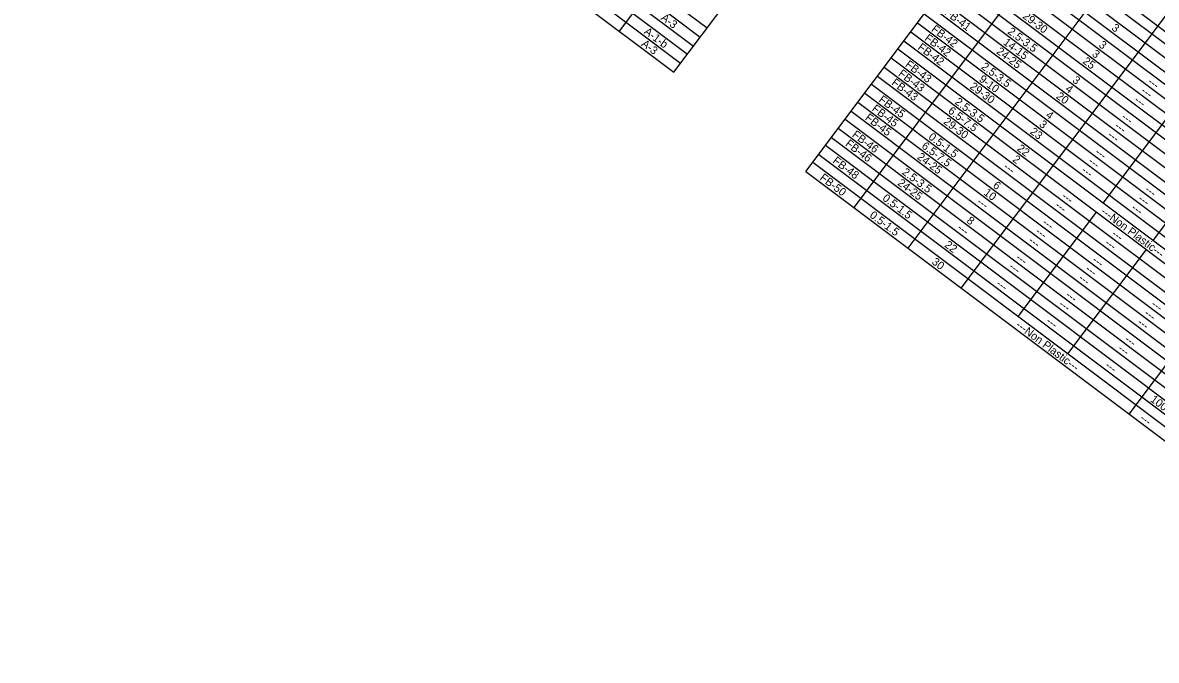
# Model space of a CAD drawing. Extents: x 627484.2 to 627517.5, y 367968.7 to 367996.9.
# Drawn here: x 627503.39 to 627511.18, y 367968.68 to 367973.07 of the extents above; entities that cross this region are included whole.
import ezdxf

# ---------------------------------------------------------------- set-up
doc = ezdxf.new("R2010")
doc.units = 0
doc.layers.add('Default', color=7, linetype='Continuous')

msp = doc.modelspace()

# ---------------------------------------------------------------- linework, layer by layer
at = {"layer": 'Default'}
for p, q in [((627503.5708, 367976.3272), (627508.046, 367972.9667)), ((627503.6176, 367976.3896), (627508.0929, 367973.0291)), ((627503.524, 367976.2648), (627507.9992, 367972.9043)), ((627503.483, 367976.2103), (627507.9582, 367972.8497)), ((627503.4361, 367976.1479), (627507.9114, 367972.7874)), ((627503.3893, 367976.0855), (627507.8646, 367972.725)), ((627507.8646, 367972.725), (627509.6531, 367975.1069)), ((627507.4903, 367973.006), (627508.8954, 367974.8772)), ((627508.7721, 367972.0435), (627510.5607, 367974.4254)), ((627509.1034, 367971.7947), (627510.892, 367974.1766)), ((627509.4738, 367971.5166), (627511.2623, 367973.8985)), ((627510.1245, 367973.8445), (627514.5997, 367970.484)), ((627510.0835, 367973.79), (627514.5588, 367970.4295)), ((627510.0367, 367973.7276), (627514.5119, 367970.3671)), ((627509.8402, 367971.2415), (627511.6288, 367973.6233)), ((627509.9489, 367973.6106), (627514.4241, 367970.2501)), ((627509.9898, 367973.6652), (627514.4651, 367970.3047)), ((627509.902, 367973.5483), (627514.3773, 367970.1878)), ((627509.8552, 367973.4859), (627514.3304, 367970.1254)), ((627509.7674, 367973.3689), (627514.2426, 367970.0084)), ((627509.8083, 367973.4235), (627514.2836, 367970.063)), ((627509.7205, 367973.3066), (627514.1958, 367969.9461)), ((627510.8156, 367971.8259), (627511.9162, 367973.2916)), ((627509.6737, 367973.2442), (627514.1489, 367969.8837)), ((627509.5859, 367973.1273), (627514.0611, 367969.7667)), ((627509.6269, 367973.1818), (627514.1021, 367969.8213)), ((627509.539, 367973.0649), (627514.0143, 367969.7044)), ((627509.4922, 367973.0025), (627513.9674, 367969.642)), ((627511.1586, 367971.5683), (627512.2593, 367973.034)), ((627509.4454, 367972.9401), (627513.9206, 367969.5796)), ((627509.3575, 367972.8232), (627513.8328, 367969.4627)), ((627509.4044, 367972.8856), (627513.8796, 367969.5251)), ((627509.3107, 367972.7608), (627513.786, 367969.4003)), ((627510.9941, 367970.375), (627512.7827, 367972.7568)), ((627509.2639, 367972.6984), (627513.7391, 367969.3379)), ((627509.1761, 367972.5815), (627513.6513, 367969.221)), ((627509.2229, 367972.6439), (627513.6981, 367969.2834)), ((627509.1292, 367972.5191), (627513.6045, 367969.1586)), ((627509.0824, 367972.4567), (627513.5576, 367969.0962)), ((627509.0414, 367972.4022), (627513.5166, 367969.0417)), ((627508.9477, 367972.2774), (627513.423, 367968.9169)), ((627508.9946, 367972.3398), (627513.4698, 367968.9793)), ((627508.9067, 367972.2228), (627513.382, 367968.8623)), ((627508.8599, 367972.1605), (627513.3352, 367968.8)), ((627508.7721, 367972.0435), (627513.2473, 367968.683)), ((627508.8189, 367972.1059), (627513.2942, 367968.7454)), ((627510.2301, 367971.0462), (627510.7687, 367971.7635)), ((627510.5732, 367970.7886), (627511.1118, 367971.5059))]:
    msp.add_line(p, q, dxfattribs=at)

# ---------------------------------------------------------------- texts
for s, p in [('FB-41', (627509.7204, 367973.126)), ('29-30', (627510.2571, 367973.1009)), ('A-3', (627507.7712, 367973.0899)), ('FB-42', (627509.6299, 367973.011)), ('3', (627510.8681, 367973.0201)), ('A-1-b', (627507.6548, 367972.9945)), ('FB-42', (627509.5831, 367972.9486)), ('2.5-3.5', (627510.1541, 367972.9954)), ('A-3', (627507.6365, 367972.9106)), ('FB-42', (627509.5363, 367972.8862)), ('24-25', (627510.0766, 367972.8585)), ('14-15', (627510.1235, 367972.9208)), ('3', (627510.7803, 367972.9031)), ('25', (627510.6698, 367972.791)), ('3', (627510.7335, 367972.8408)), ('FB-43', (627509.403, 367972.7059)), ('FB-43', (627509.4498, 367972.7683)), ('2.5-3.5', (627509.9726, 367972.7537)), ('FB-43', (627509.3561, 367972.6435)), ('9-10', (627509.9572, 367972.6677)), ('3', (627510.5988, 367972.6614)), ('---', (627511.1174, 367972.65)), ('29-30', (627509.8941, 367972.6175)), ('20', (627510.4873, 367972.5501)), ('4', (627510.5504, 367972.6003)), ('---', (627511.0706, 367972.5876)), ('FB-45', (627509.2209, 367972.4646)), ('FB-45', (627509.2678, 367972.527)), ('2.5-3.5', (627509.7911, 367972.512)), ('---', (627511.0237, 367972.5253)), ('FB-45', (627509.1741, 367972.4023)), ('6.5-7.5', (627509.7442, 367972.4496)), ('4', (627510.4157, 367972.4209)), ('---', (627510.9359, 367972.4083)), ('29-30', (627509.7127, 367972.3758)), ('3', (627510.3705, 367972.3574)), ('---', (627510.8891, 367972.3459)), ('FB-46', (627509.0854, 367972.286)), ('0.5-1.5', (627509.6096, 367972.2703)), ('23', (627510.3074, 367972.3072)), ('---', (627510.8422, 367972.2836)), ('FB-46', (627509.0385, 367972.2236)), ('6.5-7.5', (627509.5628, 367972.208)), ('22', (627510.2182, 367972.1913)), ('FB-48', (627508.9513, 367972.1062)), ('24-25', (627509.5321, 367972.1334)), ('2', (627510.1876, 367972.1167)), ('---', (627510.7076, 367972.1042)), ('---', (627510.7544, 367972.1666)), ('2.5-3.5', (627509.4281, 367972.0286)), ('---', (627510.1245, 367972.0666)), ('---', (627510.6608, 367972.0419)), ('FB-50', (627508.8628, 367971.9898)), ('24-25', (627509.3975, 367971.9541)), ('6', (627510.0529, 367971.9375)), ('0.5-1.5', (627509.2934, 367971.8493)), ('10', (627509.9897, 367971.8874)), ('---', (627510.5261, 367971.8625)), ('---', (627511.0975, 367971.909)), ('---', (627509.943, 367971.8249)), ('---', (627510.4793, 367971.8002)), ('---', (627511.0038, 367971.7843)), ('---', (627511.0506, 367971.8466)), ('0.5-1.5', (627509.2056, 367971.7324)), ('8', (627509.872, 367971.6953)), ('---Non Plastic---', (627510.7952, 367971.758)), ('---', (627509.8084, 367971.6455)), ('---', (627510.3914, 367971.6832)), ('---', (627510.2978, 367971.5585)), ('---', (627510.3446, 367971.6209)), ('---', (627510.8691, 367971.6049)), ('22', (627509.7206, 367971.5286)), ('---', (627510.8223, 367971.5426)), ('30', (627509.6326, 367971.4118)), ('---', (627510.21, 367971.4415)), ('---', (627510.7345, 367971.4256)), ('---', (627510.1631, 367971.3792)), ('---', (627510.6877, 367971.3633)), ('---', (627510.0753, 367971.2622)), ('---', (627510.6408, 367971.3009)), ('---', (627510.553, 367971.1839)), ('---', (627510.5062, 367971.1216)), ('---', (627511.1399, 367971.1212)), ('---', (627511.0931, 367971.0588)), ('---Non Plastic---', (627510.2098, 367970.9783)), ('---', (627510.4183, 367971.0046)), ('---', (627511.0462, 367970.9964)), ('---', (627510.9584, 367970.8795)), ('---', (627510.9116, 367970.8171)), ('---', (627510.8238, 367970.7002)), ('100', (627511.1348, 367970.4666)), ('---', (627511.0634, 367970.3373))]:
    msp.add_text(s, height=0.055, rotation=323.09678, dxfattribs=at).set_placement(p)

doc.saveas('drawing.dxf')
